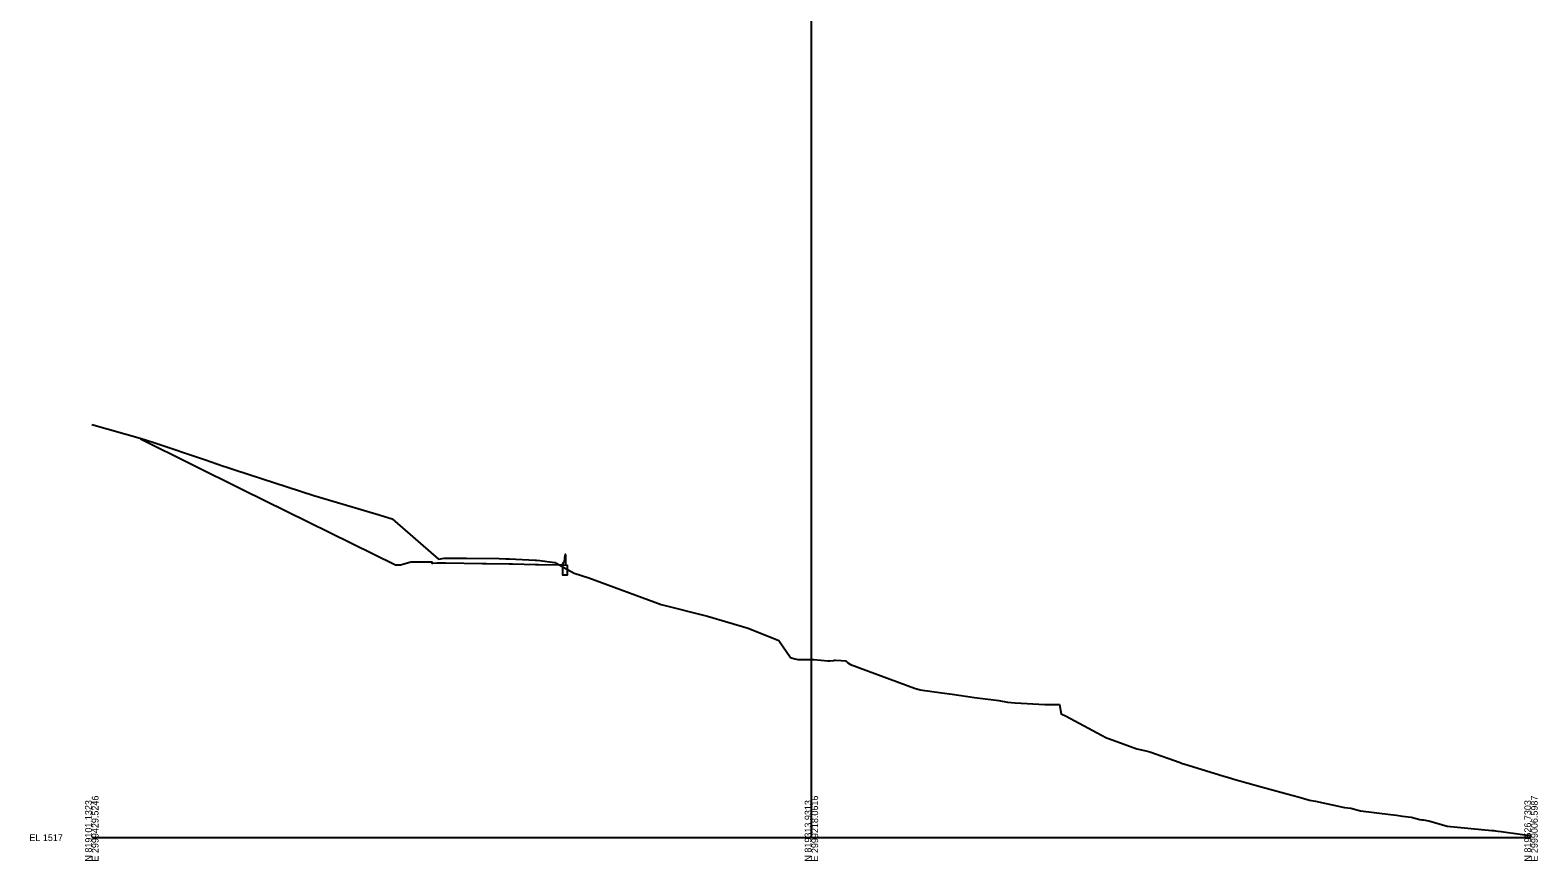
# Model space of a CAD drawing. Extents: x -26 to 603, y -10 to 4805.
# Drawn here: x -26 to 603, y -10 to 337 of the extents above; entities that cross this region are included whole.
import ezdxf

# ---------------------------------------------------------------- set-up
doc = ezdxf.new("R2010")
doc.units = 0
for name, color, linetype in [('DESIGN - SCRATCH - User 1', 7, 'Continuous'), ('DESIGN - SHEET - Light Grid', 7, 'Continuous'), ('DESIGN - TYPICAL - Finished Grade and Subgrade', 7, 'Continuous'), ('SURVEY - GROUND - Top of Ground', 7, 'Continuous')]:
    doc.layers.add(name, color=color, linetype=linetype)

msp = doc.modelspace()

# ---------------------------------------------------------------- linework, layer by layer
at = {"layer": 'DESIGN - SCRATCH - User 1'}
for p, q in [((196.25, 113.9), (196.25, 113.67)), ((196.71, 114.58), (196.27, 113.95)), ((197.16, 117.87), (196.86, 114.97)), ((197.67, 117.92), (197.22, 117.92)), ((197.67, 113.67), (197.67, 117.92))]:
    msp.add_line(p, q, dxfattribs=at)
msp.add_lwpolyline([(196.25, 113.67), (196.25, 109.53), (198.25, 109.53), (198.25, 113.53)], dxfattribs=at)
for centre, radius, start, end in [((196.33, 113.9), 0.0833, 145.00798, 180), ((196.03, 115.06), 0.833, 325.00798, 353.99099)]:
    msp.add_arc(centre, radius, start, end, dxfattribs=at)
at = {"layer": 'DESIGN - SHEET - Light Grid'}
for p, q in [((300, 0), (300, 516.44)), ((0, 0), (300, 0)), ((300, 0), (600, 0))]:
    msp.add_line(p, q, dxfattribs=at)
at = {"layer": 'DESIGN - TYPICAL - Finished Grade and Subgrade'}
msp.add_lwpolyline([(20.31, 166.15), (62.88, 145.12), (126.68, 113.62), (127.92, 113.62), (128.69, 113.63), (129.61, 113.93), (132.94, 114.97), (133.72, 114.96), (134.81, 114.95), (138.75, 114.9), (139.06, 114.9), (140.47, 114.88), (141.37, 114.87), (141.76, 114.86), (141.77, 114.38), (142.17, 114.41), (143.78, 114.55), (147.41, 114.49), (162.89, 114.24), (164.57, 114.21), (173.96, 114.05), (175.37, 114.03), (185.02, 113.87), (186.17, 113.85), (196.25, 113.67), (198.25, 113.53)], dxfattribs=at)
at = {"layer": 'SURVEY - GROUND - Top of Ground'}
msp.add_lwpolyline([(0, 172.15), (20.15, 166.53), (25.84, 164.71), (47.34, 157.39), (54.46, 154.98), (56.36, 154.36), (59.58, 153.3), (92.53, 142.59), (118.45, 134.9), (125.2, 132.8), (126.3, 131.84), (144.58, 116), (146.9, 116.45), (148.42, 116.51), (150.53, 116.47), (151.28, 116.49), (152.13, 116.49), (156.17, 116.44), (169.88, 116.26), (172.67, 116.23), (174.19, 116.18), (184.83, 115.68), (185.43, 115.62), (186.79, 115.48), (191.88, 114.84), (193.15, 114.66), (196.78, 112.53), (201.16, 110.16), (207.28, 108.22), (237.42, 97.16), (256.62, 92.3), (273.61, 87.27), (286.44, 82.13), (291.28, 75), (293.12, 74.5), (293.8, 74.32), (294.33, 74.22), (300.21, 74.19), (300.98, 74.2), (306.82, 73.69), (307.74, 73.6), (309.15, 73.87), (309.58, 73.93), (310.08, 73.89), (312.42, 73.81), (314.24, 73.73), (315.23, 72.88), (316.28, 72.14), (343.02, 62.33), (345.29, 61.53), (354.42, 60.3), (358.62, 59.76), (367.93, 58.42), (378.19, 57.16), (381.73, 56.45), (384.96, 56.16), (397.33, 55.42), (401.94, 55.47), (403.43, 55.51), (404.12, 51.62), (406.16, 50.56), (420.93, 42.72), (423.04, 41.55), (424.21, 41.12), (435.67, 37.04), (438.92, 36.23), (441.11, 35.72), (453.7, 31.24), (454.62, 30.93), (455.23, 30.74), (471.96, 25.55), (474.45, 24.87), (476.13, 24.36), (488.06, 20.99), (498.82, 18.15), (502.92, 16.97), (507.64, 15.61), (510.17, 15.13), (522.22, 12.53), (524.81, 12.2), (528.87, 11.13), (541.48, 9.67), (543.9, 9.29), (546.41, 8.99), (550.08, 8.46), (550.57, 8.32), (553.63, 7.48), (554.5, 7.44), (555.02, 7.38), (557.37, 6.92), (565.02, 4.76), (583.69, 3.02), (584.51, 2.89), (585.22, 2.8), (586.2, 2.7), (587.6, 2.5), (595.49, 1.45), (596.43, 1.34), (597.31, 1.2), (597.75, 1.14), (598.57, 1.06), (599.36, 0.97), (600, 0.91)], dxfattribs=at)

# ---------------------------------------------------------------- texts
at = {"layer": 'DESIGN - SHEET - Light Grid'}
for s, p in [('N 819101.1323', (0, -10)), ('E 2999429.5246', (2.8, -10)), ('N 819313.9313', (300, -10)), ('E 2999218.0616', (302.8, -10)), ('N 819526.7303', (600, -10)), ('E 2999006.5987', (602.8, -10))]:
    msp.add_text(s, height=2.8, rotation=90, dxfattribs=at).set_placement(p)
msp.add_text('EL 1517', height=2.8, dxfattribs=at).set_placement((-26, -1.4))

doc.saveas('drawing.dxf')
